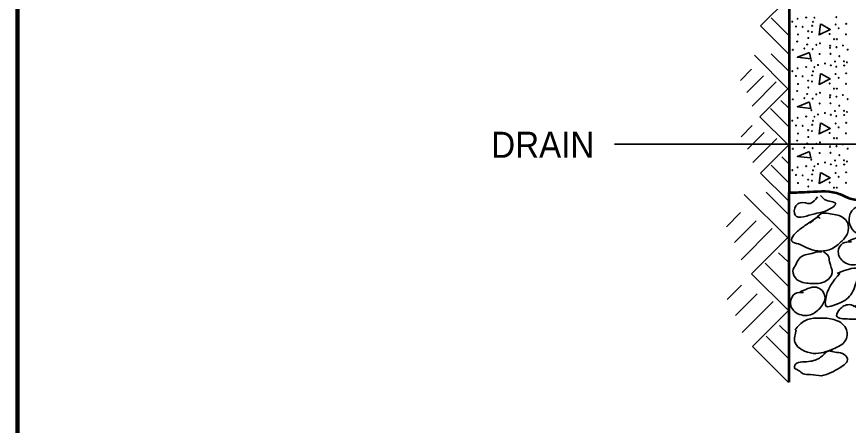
# Model space of a CAD drawing. Extents: x 442 to 1297, y -1132 to -588.
# Drawn here: x 499 to 575.6, y -1002.2 to -964.6 of the extents above; entities that cross this region are included whole.
import ezdxf

# ---------------------------------------------------------------- set-up
doc = ezdxf.new("R2010")
doc.units = 0
doc.header["$LTSCALE"] = 0.96
doc.layers.add('1', color=7, linetype='Continuous', lineweight=35)

msp = doc.modelspace()

# ---------------------------------------------------------------- linework, layer by layer
at = {"layer": '1', "lineweight": 53}
for p, q in [((570.1476, -886.6076), (570.1476, -980.7675)), ((570.1476, -886.6076), (570.1476, -980.5452)), ((570.1476, -998.2092), (570.1476, -980.7675))]:
    msp.add_line(p, q, dxfattribs=at)
at = {"layer": '1'}
for p, q in [((570.0996, -962.8316), (567.5316, -965.3996)), ((570.0996, -966.2636), (568.5156, -964.6796)), ((570.0996, -967.9676), (567.5316, -965.3996)), ((570.0996, -971.2556), (566.9556, -968.1116)), ((570.0996, -969.5516), (568.5156, -967.9676)), ((566.6916, -969.4076), (565.6836, -970.4396)), ((567.7956, -970.0076), (566.2596, -971.5436)), ((568.9476, -970.5596), (566.7396, -972.7916)), ((570.0996, -971.1356), (567.4596, -973.7756)), ((570.0996, -972.9596), (569.4036, -972.2876)), ((570.0996, -974.6876), (568.4436, -973.0316)), ((570.0996, -976.3916), (567.4596, -973.7756)), ((566.7636, -974.5916), (565.7316, -975.6236)), ((567.8676, -975.2156), (566.3316, -976.7516)), ((569.0196, -975.7676), (566.8116, -977.9756)), ((621.7985, -976.3102), (554.0822, -976.3102)), ((570.0996, -976.3916), (567.5316, -978.9596)), ((570.0996, -978.0956), (569.4756, -977.4716)), ((570.0996, -979.8236), (568.5156, -978.2396)), ((570.0996, -981.5276), (567.5316, -978.9596)), ((570.0856, -982.7812), (568.041, -980.7365)), ((570.0856, -984.9808), (566.0273, -980.9224)), ((565.6865, -982.5953), (564.3853, -983.9275)), ((567.1116, -983.3698), (565.1289, -985.3525)), ((568.5986, -984.0824), (565.7485, -986.9635)), ((570.0856, -984.8259), (566.6778, -988.2337)), ((570.0856, -987.1803), (569.1872, -986.3129)), ((570.0856, -989.4109), (567.948, -987.2733)), ((570.0856, -991.6105), (566.6778, -988.2337)), ((565.7794, -989.287), (564.4473, -990.6191)), ((567.2045, -990.0925), (565.2218, -992.0752)), ((568.6915, -990.805), (565.8414, -993.6552)), ((570.0856, -991.6105), (566.7708, -994.9253)), ((570.0856, -993.8101), (569.2802, -993.0046)), ((570.0856, -996.0406), (568.041, -993.9959)), ((570.0856, -998.2402), (566.7708, -994.9253))]:
    msp.add_line(p, q, dxfattribs=at)
at = {"layer": '1', "lineweight": 158}
msp.add_lwpolyline([(1290.7447, -594.0679), (499.0447, -594.1679), (499.1447, -1120.1679)], dxfattribs=at)
at = {"layer": '1'}
for points in [[(573.0974, -965.2547), (573.9374, -965.7347), (572.9054, -966.2387), (573.0494, -965.2307)], [(570.1476, -965.9222), (570.1694, -965.9267), (570.1476, -965.9501)], [(572.0414, -967.8467), (570.9134, -968.3027), (572.1614, -968.4467), (572.0414, -967.8947)], [(573.0974, -969.8147), (573.9374, -970.2947), (572.9054, -970.7987), (573.0494, -969.7907)], [(570.1476, -970.4822), (570.1694, -970.4867), (570.1476, -970.5101)], [(572.0414, -972.4067), (570.9134, -972.8627), (572.1614, -973.0067), (572.0414, -972.4547)], [(573.0974, -974.3747), (573.9374, -974.8547), (572.9054, -975.3587), (573.0494, -974.3507)], [(570.1476, -975.0422), (570.1694, -975.0467), (570.1476, -975.0701)], [(572.0414, -976.9667), (570.9134, -977.4227), (572.1614, -977.5667), (572.0414, -977.0147)], [(573.0974, -978.9347), (573.9374, -979.4147), (572.9054, -979.9187), (573.0494, -978.9107)]]:
    msp.add_lwpolyline(points, dxfattribs=at)
for centre in [(571.7181, -964.6409), (572.4814, -964.6568), (574.5013, -964.6091), (570.4458, -965.0227), (570.7797, -965.4682), (570.9388, -964.7523), (572.2747, -965.4045), (572.3542, -965.0386), (574.4375, -965.2772), (575.4077, -965.2136), (570.9705, -966.2), (571.3999, -965.5), (571.9089, -965.8978), (572.2588, -965.9773), (573.8809, -966.1523), (574.708, -965.6273), (575.3841, -966.1868), (570.8911, -966.8522), (571.9248, -966.5182), (574.2786, -966.6296), (574.5489, -966.6296), (570.4934, -967.6101), (571.559, -967.4987), (571.8135, -967.1227), (572.3224, -967.5465), (572.6564, -967.1545), (572.9904, -967.0114), (573.9128, -967.4351), (573.9287, -967.2341), (574.5171, -967.3715), (575.1055, -967.2181), (575.5441, -967.5941), (572.9585, -967.9919), (573.9605, -967.976), (574.7716, -968.1986), (571.7181, -969.2009), (572.1951, -968.6123), (572.4814, -969.2168), (572.8154, -969.0101), (573.4515, -968.8668), (573.9923, -969.0418), (574.3739, -968.6918), (574.5013, -969.1691), (575.201, -968.6759), (575.2168, -969.0577), (575.4805, -968.7714), (570.4458, -969.5827), (570.7797, -970.0282), (570.9388, -969.3123), (571.3999, -970.06), (572.2747, -969.9645), (572.3542, -969.5986), (574.4375, -969.8372), (575.4077, -969.7736), (570.9705, -970.76), (571.9089, -970.4578), (572.2588, -970.5373), (573.8809, -970.7123), (574.708, -970.1873), (575.3841, -970.7468), (570.8911, -971.4122), (571.9248, -971.0782), (572.9904, -971.5714), (574.2786, -971.1896), (574.5489, -971.1896), (570.4934, -972.1701), (571.559, -972.0587), (571.8135, -971.6827), (572.3224, -972.1065), (572.6564, -971.7145), (573.9128, -971.9951), (573.9287, -971.7941), (574.5171, -971.9315), (575.1055, -971.7781), (575.5441, -972.1541), (572.9585, -972.5519), (573.9605, -972.536), (574.7716, -972.7586), (570.9388, -973.8723), (571.7181, -973.7609), (572.1951, -973.1723), (572.4814, -973.7768), (572.8154, -973.5701), (573.4515, -973.4268), (573.9923, -973.6018), (574.3739, -973.2518), (574.5013, -973.7291), (575.201, -973.2359), (575.2168, -973.6177), (575.4805, -973.3314), (570.4458, -974.1427), (570.7797, -974.5882), (571.3999, -974.62), (572.2747, -974.5245), (572.3542, -974.1586), (574.4375, -974.3972), (575.4077, -974.3336), (570.9705, -975.32), (571.9089, -975.0178), (572.2588, -975.0973), (573.8809, -975.2723), (574.708, -974.7473), (575.3841, -975.3068), (570.8911, -975.9722), (571.9248, -975.6382), (572.9904, -976.1314), (574.2786, -975.7496), (574.5489, -975.7496), (570.4934, -976.7301), (571.559, -976.6187), (571.8135, -976.2427), (572.3224, -976.6665), (572.6564, -976.2745), (573.9128, -976.5551), (573.9287, -976.3541), (574.5171, -976.4915), (575.1055, -976.3381), (575.5441, -976.7141), (572.9585, -977.1119), (573.9605, -977.096), (574.7716, -977.3186), (570.9388, -978.4323), (571.7181, -978.3209), (572.1951, -977.7323), (572.4814, -978.3368), (572.8154, -978.1301), (573.4515, -977.9868), (573.9923, -978.1618), (574.3739, -977.8118), (574.5013, -978.2891), (575.201, -977.7959), (575.2168, -978.1777), (575.4805, -977.8914), (570.4458, -978.7027), (570.7797, -979.1482), (571.3999, -979.18), (572.2747, -979.0845), (572.3542, -978.7186), (574.4375, -978.9572), (575.4077, -978.8936), (570.9705, -979.88), (571.9089, -979.5778), (572.2588, -979.6573), (573.8809, -979.8323), (574.708, -979.3073), (575.3841, -979.8668), (571.9248, -980.1982), (572.9904, -980.6914), (574.2786, -980.3096), (574.5489, -980.3096)]:
    msp.add_circle(centre, 0.0318, dxfattribs=at)
at = {"layer": '1', "lineweight": 53}
msp.add_spline([(570.1476, -980.7675), (572.0496, -980.6901), (574.8408, -980.8969), (575.7712, -981.3106), (578.1489, -981.2071), (580.3199, -981.0003), (583.0077, -981.0003), (586.0057, -980.8969), (587.0395, -980.7935), (590.0375, -981.2071), (593.0355, -981.1037), (594.6895, -981.1037), (598.928, -981.3106), (600.9956, -981.0003), (602.3395, -980.5867), (605.3375, -980.7935), (607.1983, -981.0003), (612.3673, -981.414), (614.2281, -981.3106), (617.2261, -981.0003), (619.2937, -980.7935), (623.739, -981.5174), (624.9795, -981.0003), (626.7369, -980.6901), (630.2518, -980.6901), (634.5937, -980.4833), (641.0032, -980.4833), (645.4485, -980.5867), (649.3769, -981.414), (652.0647, -981.414), (655.8898, -981.0003), (658.9911, -981.0003), (663.8499, -980.6901), (667.8817, -980.7935), (671.8101, -980.8969), (675.7476, -980.7675)], degree=3, dxfattribs=at)
at = {"layer": '1'}
for points in [[(572.752, -981.1493), (572.0903, -981.7508), (571.1881, -981.6907), (570.7671, -981.9914), (570.7069, -982.8335), (572.5114, -982.7132), (573.2933, -982.5328), (574.4361, -981.7508), (573.4136, -981.3899), (573.0527, -981.029)], [(577.1768, -981.4808), (576.455, -982.0221), (576.034, -982.3228), (575.7332, -983.7063), (576.2746, -984.428), (577.8384, -984.3679), (578.7407, -983.9469), (578.9813, -982.9243), (578.6204, -982.1424), (577.8384, -981.7214), (576.8761, -981.7214)], [(572.993, -983.1427), (572.8727, -983.0224), (572.5719, -983.1427), (571.6096, -983.8043), (570.8276, -984.4058), (570.587, -984.6464), (570.4066, -985.2479), (571.0081, -985.4885), (571.79, -985.8494), (573.8351, -986.0298), (574.9177, -985.308), (575.5192, -984.5261), (575.5192, -983.5036), (574.617, -982.8419), (573.9554, -982.7217), (573.2336, -982.6615), (572.6321, -983.0825), (572.0907, -983.5637)], [(575.8801, -985.31), (575.0981, -985.4303), (574.6771, -986.2123), (575.2184, -987.1746), (576.5417, -987.3551), (577.4439, -986.6934), (577.865, -985.6709), (577.083, -984.8288), (576.3011, -984.9491), (575.5793, -985.2499)], [(573.1516, -986.2314), (572.7907, -986.2314), (572.0689, -986.4118), (571.5275, -986.5321), (570.9261, -987.0735), (570.7456, -987.4344), (570.505, -987.9757), (570.8659, -988.7576), (572.0689, -989.1185), (573.5726, -988.8779), (574.1139, -988.1562), (573.8733, -987.1336), (573.7531, -986.5923), (573.332, -986.2314)], [(574.8199, -988.2083), (573.4967, -990.7346), (573.5568, -991.2158), (574.2184, -991.1556), (575.7222, -990.3136), (576.3838, -988.87), (576.5642, -987.9076), (574.5793, -988.2083)], [(571.469, -989.961), (570.687, -990.0813), (570.266, -990.8633), (570.8073, -991.8256), (572.1306, -992.0061), (573.0328, -991.3444), (573.4539, -990.3219), (572.6719, -989.4798), (571.89, -989.6001), (571.1682, -989.9009)], [(576.4495, -991.382), (575.6676, -991.0812), (575.1864, -991.2015), (574.8255, -991.5023), (574.5247, -992.1038), (575.6676, -992.4045), (576.6299, -992.4045), (577.6525, -992.3444), (578.1938, -992.1038), (578.1337, -991.6226), (577.7126, -991.1414), (577.3517, -991.0211), (576.8104, -991.0812), (576.5096, -991.1414), (576.0886, -991.2617)], [(570.8125, -993.3997), (570.6922, -994.5425), (572.3764, -995.5651), (574.241, -995.144), (575.3237, -994.4222), (575.444, -993.3997), (574.4215, -992.4975), (573.1583, -992.317), (572.1358, -992.3772), (571.5945, -992.5576), (570.6922, -993.3997)], [(574.1517, -995.3367), (573.6705, -995.3969), (573.3097, -995.6976), (572.9488, -995.9984), (572.4074, -996.2389), (572.1067, -996.2991), (571.3849, -996.3592), (570.7233, -996.5998), (570.6631, -996.9006), (571.024, -997.1412), (571.445, -997.4419), (572.1067, -997.5021), (573.1292, -997.6224), (574.0314, -997.3216), (574.8134, -996.9006), (575.5352, -996.0585), (575.054, -995.5773), (574.3923, -995.457), (573.7908, -995.3367)]]:
    msp.add_spline(points, degree=3, dxfattribs=at)

# ---------------------------------------------------------------- texts
at = {"layer": '1', "width": 0.95}
msp.add_text('DRAIN', height=2.4, dxfattribs=at).set_placement((542.7341, -977.5572))

doc.saveas('drawing.dxf')
